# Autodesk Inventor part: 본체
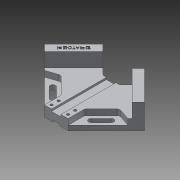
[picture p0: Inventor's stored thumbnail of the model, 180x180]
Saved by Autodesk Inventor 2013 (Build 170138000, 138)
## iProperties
Created: 2019-04
Part Number: 본체
Material: 알루미늄 6061
Document SubType Name: Modeling
Designer: Administrator
Density: 2.71 g/cm^3
Mass: 603.737 g
Surface Area: 426.536 cm^2
Volume: 222.781 cm^3
Author: Administrator
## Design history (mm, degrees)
sketch "스케치1"
  geometry: L1 (0, 0)-(0, -20); L2 (0, -169.706)-(35.355, -134.35); L3 (84.853, -84.853)-(20, -20); L4 (35.355, -134.35)-(14.005, -113); L5 (14.005, -113)-(0, -113); L6 (20, -20)-(0, -20); L7 (35.355, -134.35)-(84.853, -84.853); L8 (0, -113)-(0, -169.706); L9 (20, -20)-(0, 0); L10 (0, -20)-(0, -113)
  constraints: 20 end point, 10 perpendicular, 3 vertical, 2 parallel
  dimensions: "d25" = 45 deg angle of L1 L3; "d26" = 120 distance of L2.start L3.start; "d28" = 20 distance of L3.end L1.end; "d29" = 50 distance of L2.start L2.end; "d41" = 93 distance of L1.end L5.end
extrude "돌출1" new body sketch "스케치1" distance "d31" = 18; taper "d32" = 0 deg
sketch "스케치2"
  geometry: L1 (-84.853, 84.853)-(-20, 20) reference; L2 (-14.005, 113)-(-35.355, 134.35) reference; L3 (-35.355, 134.35)-(-84.853, 84.853) reference; L4 (-35.355, 134.35)-(-24.749, 123.744); L5 (-24.749, 123.744)-(-74.246, 74.246); L6 (-84.853, 84.853)-(-35.355, 134.35); L7 (-84.853, 84.853)-(-74.246, 74.246); 1 further point
  constraints: 8 end point, 2 point on line, 1 collinear, 1 perpendicular
  dimensions: "d33" = 15 distance of L2.end L4.end
extrude "돌출2" join sketch "스케치2" distance "d34" = 24; taper "d35" = 0 deg
sketch "스케치3"
  geometry: L1 (-74.246, 74.246)-(-20, 20) reference; L2 (0, 20)-(0, 113) reference; L3 (-35.355, 134.35)-(-84.853, 84.853) reference; L4 (-84.853, 84.853)-(-74.246, 74.246) reference; L5 (-74.246, 74.246)-(-24.749, 123.744) reference; L6 (-24.749, 123.744)-(-35.355, 134.35) reference; L7 (-70.711, 70.711)-(-49.497, 77.782); L8 (-49.497, 77.782)-(-20, 48.284); L9 (-20, 48.284)-(-20, 20); L10 (-70.711, 70.711)-(-20, 20); 1 further point
  constraints: 8 end point, 3 parallel, 1 point on line
  dimensions: "d36" = 20 distance from line of L3 L7.start; "d37" = 20 distance between parallel lines of L8 L10; "d38" = 30 distance from line of L7.end L3
extrude "돌출3" cut sketch "스케치3" distance "d39" = 10; taper "d40" = 0 deg
sketch "스케치4"
  geometry: L1 (-20, 20)-(0, 20) reference; L2 (0, 20)-(0, 113) reference; L3 (0, 20)-(0, 113); L4 (-8, 113)-(-8, 20); L5 (0, 20)-(-8, 20); L6 (0, 113)-(-14.005, 113) reference; L7 (-8, 113)-(0, 113); 1 further point
  constraints: 8 end point, 2 collinear, 2 perpendicular, 1 point on line
  dimensions: "d42" = 8 distance of L4.start L2.end; "d43" = 93 distance of L4.start L4.end (derived)
extrude "돌출4" cut sketch "스케치4" distance "d44" = 3.5; taper "d45" = 0 deg
sketch "스케치6"
  geometry: L1 (0, -20)-(-6, -20); L2 (-6, -20)-(-6, -113); L3 (-6, -113)-(0, -113); L4 (0, -113)-(0, -20); 1 further point
  constraints: 8 end point, 2 parallel, 1 horizontal, 1 perpendicular
  dimensions: "d51" = 6 distance of L3.end L2.end; "d52" = 93 distance of L2.end L1.end
extrude "돌출5" cut sketch "스케치6" distance "d53" = 3; taper "d54" = 0 deg
sketch "스케치7"
  geometry: L1 (-20, -20)-(-6, -20) reference; L2 (0, -20)-(0, -113) reference; 3 further points
  constraints: 1 vertical alignment
  dimensions: "d55" = 6 distance from line of L1 point (-14, -26); "d56" = 12 distance of point (-14, -26) point (-14, -38); "d57" = 14 distance from line of L2 point (-14, -26)
hole "구멍1" sketch "스케치7" at (-14, -26), (-14, -38) diameter "d58" = 4.5; stored, may be unused: countersink angle "d62" = 90 deg, drill point angle "d64" = 118 deg; dims "d59" = 6, "d60" = 8, "d61" = 10, "d63" = 8
fillet "모깎기1" dims "d65" = 5
sketch "스케치8"
  geometry: L1 (-35.355, 134.35)-(-84.853, 84.853) reference; L2 (-24.749, 123.744)-(-35.355, 134.35) reference; 2 further points
  constraints: 1 other
  dimensions: "d66" = 7.5 distance from line of L1 point (-54.801, 104.298); "d67" = 35 distance from line of point (-54.801, 104.298) L2
feature "엠보싱1" sketch "스케치8" dims "d68" = 0.5, "d69" = 0
sketch "스케치9"
  geometry: L1 (-20, 20)-(-70.711, 70.711) reference; L2 (-52.679, 60.458)-(-35.709, 43.487); L3 (-29.345, 49.851)-(-46.315, 66.822); L4 (-35.355, 134.35)-(-84.853, 84.853) reference; L5 (-84.853, 84.853)-(-74.246, 74.246) reference; L6 (-74.246, 74.246)-(-24.749, 123.744) reference; L7 (-24.749, 123.744)-(-35.355, 134.35) reference; L8 (-65.261, 93.526)-(-66.187, 94.452) reference; L9 (-68.154, 92.197)-(-68.451, 92.428) reference; L10 (-66.153, 95.052)-(-63.587, 92.485) reference; L11 (-63.587, 92.485)-(-65.635, 90.437) reference; L12 (-65.635, 90.437)-(-65.899, 90.701) reference; L13 (-65.899, 90.701)-(-64.167, 92.432) reference; L14 (-64.167, 92.432)-(-64.997, 93.262) reference; L15 (-64.997, 93.262)-(-66.542, 91.718) reference; L16 (-66.542, 91.718)-(-66.806, 91.981) reference; L17 (-66.806, 91.981)-(-65.261, 93.526) reference; L18 (-61.687, 93.579)-(-64.781, 96.673) reference; L19 (-64.781, 96.673)-(-64.46, 96.995) reference; L20 (-64.46, 96.995)-(-61.217, 93.752) reference; L21 (-61.217, 93.752)-(-61.471, 93.497) reference; L22 (-60.939, 94.471)-(-63.784, 97.316) reference; L23 (-63.784, 97.316)-(-63.462, 97.637) reference; L24 (-63.462, 97.637)-(-61.75, 95.925) reference; L25 (-61.75, 95.925)-(-61.02, 96.654) reference; L26 (-61.02, 96.654)-(-60.776, 96.409) reference; L27 (-60.776, 96.409)-(-61.505, 95.68) reference; L28 (-61.505, 95.68)-(-60.449, 94.625) reference; L29 (-60.449, 94.625)-(-60.713, 94.361) reference; L30 (-65.563, 97.254)-(-65.827, 97.517) reference; L31 (-65.827, 97.517)-(-62.771, 100.573) reference; L32 (-62.771, 100.573)-(-61.419, 99.22) reference; L33 (-61.419, 99.22)-(-61.654, 98.985) reference; L34 (-61.879, 99.048)-(-62.824, 99.993) reference; L35 (-62.824, 99.993)-(-65.563, 97.254) reference; L36 (-62.34, 97.11)-(-62.368, 97.57) reference; L37 (-60.608, 99.619)-(-60.147, 99.599) reference; L38 (-59.053, 96.289)-(-59.337, 96.006) reference; L39 (-59.759, 100.727)-(-60.075, 100.41) reference; L40 (-58.698, 99.091)-(-58.377, 99.412) reference; L41 (-54.194, 101.533)-(-54.487, 101.825) reference; L42 (-54.487, 101.825)-(-53.383, 102.929) reference; L43 (-53.383, 102.929)-(-56.626, 106.172) reference; L44 (-56.626, 106.172)-(-56.305, 106.493) reference; L45 (-56.305, 106.493)-(-53.062, 103.25) reference; L46 (-53.062, 103.25)-(-51.963, 104.349) reference; L47 (-51.963, 104.349)-(-51.671, 104.056) reference; L48 (-51.671, 104.056)-(-54.194, 101.533) reference; L49 (-48.265, 112.039)-(-49.545, 110.758) reference; L50 (-49.545, 110.758)-(-51.047, 112.259) reference; L51 (-51.047, 112.259)-(-50.721, 112.585) reference; L52 (-50.721, 112.585)-(-49.483, 111.348) reference; L53 (-49.483, 111.348)-(-46.773, 114.058) reference; L54 (-46.773, 114.058)-(-46.509, 113.794) reference; L55 (-46.509, 113.794)-(-47.943, 112.36) reference; L56 (-47.943, 112.36)-(-47.08, 111.496) reference; L57 (-47.08, 111.496)-(-45.127, 113.449) reference; L58 (-45.127, 113.449)-(-44.863, 113.185) reference; L59 (-44.863, 113.185)-(-47.953, 110.096) reference; L60 (-46.974, 108.714)-(-44.283, 111.405) reference; L61 (-44.283, 111.405)-(-44.014, 111.137) reference; L62 (-44.014, 111.137)-(-47.046, 108.105) reference; L63 (-48.303, 109.745)-(-49.109, 108.94) reference; L64 (-49.109, 108.94)-(-49.373, 109.203) reference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; A1 r 4.5 centre (-32.527, 46.669) between (-35.709, 43.487) and (-29.345, 49.851); A2 r 4.5 centre (-49.497, 63.64) between (-46.315, 66.822) and (-52.679, 60.458); 54 further points
  constraints: 4 end point, 4 point on circle, 4 tangent, 2 centre point, 2 parallel, 1 horizontal alignment, 67 other
  dimensions: "d70" = 40 distance from line of L4 A2.centre; "d71" = 24 distance of L2.start L2.end; "d72" = 9 distance between parallel lines of L2 L3; "d73" = 10 distance from line of L5 A2.centre
extrude "돌출6" cut sketch "스케치9" stored distance "d74" = 3; taper "d75" = 0 deg
node "솔리드1"
mirror "대칭1"
mirror "대칭2"
node "투영된 루프1"
node "투영된 루프3"
